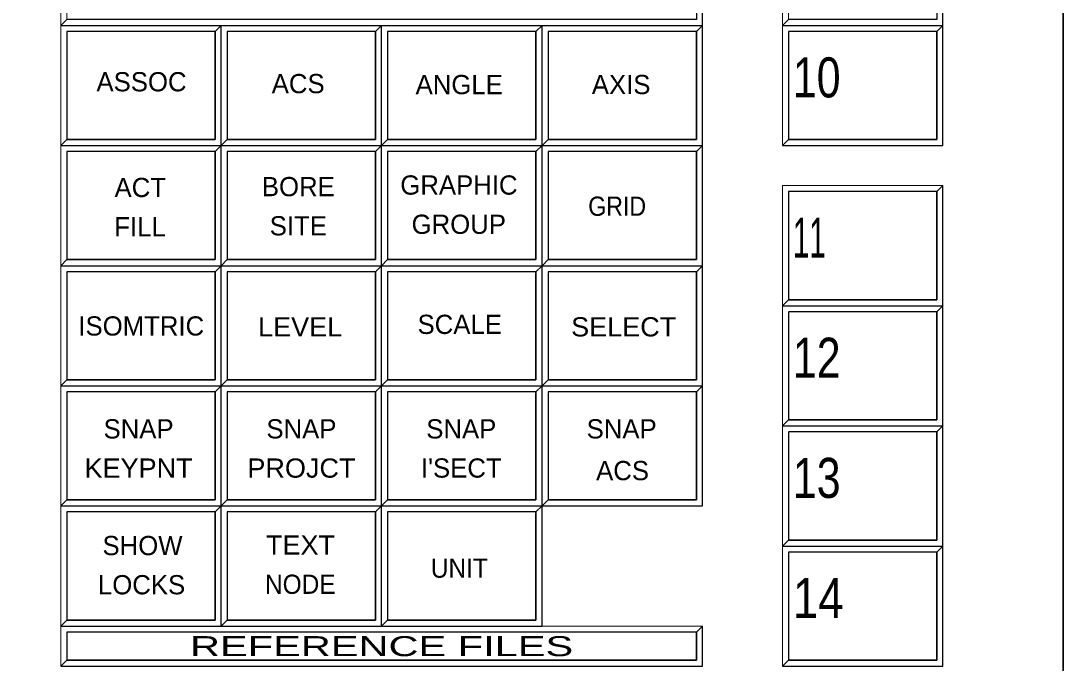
# Model space of a CAD drawing. Extents: x 95906.8 to 95923.6, y 90964.8 to 90972.8.
# Drawn here: x 95916.232 to 95918.832, y 90967.969 to 90969.573 of the extents above; entities that cross this region are included whole.
import ezdxf
from ezdxf.enums import TextEntityAlignment as Align

# ---------------------------------------------------------------- set-up
doc = ezdxf.new("R2010")
doc.units = 0
doc.header["$LTSCALE"] = 0.019
for name, color, linetype, lineweight in [('11', 7, 'Continuous', 25), ('12', 7, 'Continuous', 25), ('2', 7, 'Continuous', 13), ('21', 7, 'Continuous', 25), ('3', 7, 'Continuous', 25), ('6', 7, 'Continuous', 25), ('7', 7, 'Continuous', 35)]:
    doc.layers.add(name, color=color, linetype=linetype, lineweight=lineweight)

msp = doc.modelspace()

# ---------------------------------------------------------------- linework, layer by layer
at = {"layer": '11'}
for points in [[(95916.3473, 90969.2767), (95916.7173, 90969.2767), (95916.7173, 90969.5467), (95916.3473, 90969.5467)], [(95916.7473, 90969.2767), (95917.1173, 90969.2767), (95917.1173, 90969.5467), (95916.7473, 90969.5467)], [(95917.1473, 90969.2767), (95917.5173, 90969.2767), (95917.5173, 90969.5467), (95917.1473, 90969.5467)], [(95918.1473, 90969.2767), (95918.5173, 90969.2767), (95918.5173, 90969.5467), (95918.1473, 90969.5467)], [(95916.3473, 90968.9767), (95916.7173, 90968.9767), (95916.7173, 90969.2467), (95916.3473, 90969.2467)], [(95916.7473, 90968.9767), (95917.1173, 90968.9767), (95917.1173, 90969.2467), (95916.7473, 90969.2467)], [(95917.1473, 90968.9767), (95917.5173, 90968.9767), (95917.5173, 90969.2467), (95917.1473, 90969.2467)], [(95917.5473, 90968.9767), (95917.9173, 90968.9767), (95917.9173, 90969.2467), (95917.5473, 90969.2467)], [(95918.1473, 90968.8767), (95918.5173, 90968.8767), (95918.5173, 90969.1467), (95918.1473, 90969.1467)], [(95916.3473, 90968.6767), (95916.7173, 90968.6767), (95916.7173, 90968.9467), (95916.3473, 90968.9467)], [(95916.7473, 90968.6767), (95917.1173, 90968.6767), (95917.1173, 90968.9467), (95916.7473, 90968.9467)], [(95917.1473, 90968.6767), (95917.5173, 90968.6767), (95917.5173, 90968.9467), (95917.1473, 90968.9467)], [(95917.1473, 90968.6767), (95917.5173, 90968.6767), (95917.5173, 90968.9467), (95917.1473, 90968.9467)], [(95917.5473, 90968.6767), (95917.9173, 90968.6767), (95917.9173, 90968.9467), (95917.5473, 90968.9467)], [(95918.1473, 90968.5767), (95918.5173, 90968.5767), (95918.5173, 90968.8467), (95918.1473, 90968.8467)], [(95916.3473, 90968.3767), (95916.7173, 90968.3767), (95916.7173, 90968.6467), (95916.3473, 90968.6467)], [(95916.7473, 90968.3767), (95917.1173, 90968.3767), (95917.1173, 90968.6467), (95916.7473, 90968.6467)], [(95916.7473, 90968.3767), (95917.1173, 90968.3767), (95917.1173, 90968.6467), (95916.7473, 90968.6467)], [(95917.1473, 90968.3767), (95917.5173, 90968.3767), (95917.5173, 90968.6467), (95917.1473, 90968.6467)], [(95917.1473, 90968.3767), (95917.5173, 90968.3767), (95917.5173, 90968.6467), (95917.1473, 90968.6467)], [(95917.5473, 90968.3767), (95917.9173, 90968.3767), (95917.9173, 90968.6467), (95917.5473, 90968.6467)], [(95917.5473, 90968.3767), (95917.9173, 90968.3767), (95917.9173, 90968.6467), (95917.5473, 90968.6467)], [(95918.1473, 90968.2767), (95918.5173, 90968.2767), (95918.5173, 90968.5467), (95918.1473, 90968.5467)], [(95916.3473, 90968.0767), (95916.7173, 90968.0767), (95916.7173, 90968.3467), (95916.3473, 90968.3467)], [(95916.7473, 90968.0767), (95917.1173, 90968.0767), (95917.1173, 90968.3467), (95916.7473, 90968.3467)], [(95917.1473, 90968.0767), (95917.5173, 90968.0767), (95917.5173, 90968.3467), (95917.1473, 90968.3467)], [(95918.1473, 90967.9767), (95918.5173, 90967.9767), (95918.5173, 90968.2467), (95918.1473, 90968.2467)]]:
    msp.add_lwpolyline(points, close=True, dxfattribs=at)
at = {"layer": '12'}
msp.add_lwpolyline([(95917.5473, 90969.2767), (95917.9173, 90969.2767), (95917.9173, 90969.5467), (95917.5473, 90969.5467)], close=True, dxfattribs=at)
at = {"layer": '2'}
for points in [[(95918.1323, 90969.8617), (95918.1323, 90969.5617), (95918.1473, 90969.5767), (95918.1473, 90969.8467), (95918.5173, 90969.8467), (95918.5323, 90969.8617)], [(95916.3323, 90969.6617), (95916.3323, 90969.5617), (95916.3473, 90969.5767), (95916.3473, 90969.6467), (95917.9173, 90969.6467), (95917.9323, 90969.6617)], [(95916.3323, 90969.5617), (95916.3323, 90969.2617), (95916.3473, 90969.2767), (95916.3473, 90969.5467), (95916.7173, 90969.5467), (95916.7323, 90969.5617)], [(95916.7323, 90969.5617), (95916.7323, 90969.2617), (95916.7473, 90969.2767), (95916.7473, 90969.5467), (95917.1173, 90969.5467), (95917.1323, 90969.5617)], [(95917.1323, 90969.5617), (95917.1323, 90969.2617), (95917.1473, 90969.2767), (95917.1473, 90969.5467), (95917.5173, 90969.5467), (95917.5323, 90969.5617)], [(95917.5323, 90969.5617), (95917.5323, 90969.2617), (95917.5473, 90969.2767), (95917.5473, 90969.5467), (95917.9173, 90969.5467), (95917.9323, 90969.5617)], [(95918.1323, 90969.5617), (95918.1323, 90969.2617), (95918.1473, 90969.2767), (95918.1473, 90969.5467), (95918.5173, 90969.5467), (95918.5323, 90969.5617)], [(95916.3323, 90969.2617), (95916.3323, 90968.9617), (95916.3473, 90968.9767), (95916.3473, 90969.2467), (95916.7173, 90969.2467), (95916.7323, 90969.2617)], [(95916.7323, 90969.2617), (95916.7323, 90968.9617), (95916.7473, 90968.9767), (95916.7473, 90969.2467), (95917.1173, 90969.2467), (95917.1323, 90969.2617)], [(95917.1323, 90969.2617), (95917.1323, 90968.9617), (95917.1473, 90968.9767), (95917.1473, 90969.2467), (95917.5173, 90969.2467), (95917.5323, 90969.2617)], [(95917.5323, 90969.2617), (95917.5323, 90968.9617), (95917.5473, 90968.9767), (95917.5473, 90969.2467), (95917.9173, 90969.2467), (95917.9323, 90969.2617)], [(95918.1323, 90969.1617), (95918.1323, 90968.8617), (95918.1473, 90968.8767), (95918.1473, 90969.1467), (95918.5173, 90969.1467), (95918.5323, 90969.1617)], [(95916.3323, 90968.9617), (95916.3323, 90968.6617), (95916.3473, 90968.6767), (95916.3473, 90968.9467), (95916.7173, 90968.9467), (95916.7323, 90968.9617)], [(95916.7323, 90968.9617), (95916.7323, 90968.6617), (95916.7473, 90968.6767), (95916.7473, 90968.9467), (95917.1173, 90968.9467), (95917.1323, 90968.9617)], [(95917.1323, 90968.9617), (95917.1323, 90968.6617), (95917.1473, 90968.6767), (95917.1473, 90968.9467), (95917.5173, 90968.9467), (95917.5323, 90968.9617)], [(95917.1323, 90968.9617), (95917.1323, 90968.6617), (95917.1473, 90968.6767), (95917.1473, 90968.9467), (95917.5173, 90968.9467), (95917.5323, 90968.9617)], [(95917.5323, 90968.9617), (95917.5323, 90968.6617), (95917.5473, 90968.6767), (95917.5473, 90968.9467), (95917.9173, 90968.9467), (95917.9323, 90968.9617)], [(95918.1323, 90968.8617), (95918.1323, 90968.5617), (95918.1473, 90968.5767), (95918.1473, 90968.8467), (95918.5173, 90968.8467), (95918.5323, 90968.8617)], [(95916.3323, 90968.6617), (95916.3323, 90968.3617), (95916.3473, 90968.3767), (95916.3473, 90968.6467), (95916.7173, 90968.6467), (95916.7323, 90968.6617)], [(95916.7323, 90968.6617), (95916.7323, 90968.3617), (95916.7473, 90968.3767), (95916.7473, 90968.6467), (95917.1173, 90968.6467), (95917.1323, 90968.6617)], [(95916.7323, 90968.6617), (95916.7323, 90968.3617), (95916.7473, 90968.3767), (95916.7473, 90968.6467), (95917.1173, 90968.6467), (95917.1323, 90968.6617)], [(95917.1323, 90968.6617), (95917.1323, 90968.3617), (95917.1473, 90968.3767), (95917.1473, 90968.6467), (95917.5173, 90968.6467), (95917.5323, 90968.6617)], [(95917.1323, 90968.6617), (95917.1323, 90968.3617), (95917.1473, 90968.3767), (95917.1473, 90968.6467), (95917.5173, 90968.6467), (95917.5323, 90968.6617)], [(95917.5323, 90968.6617), (95917.5323, 90968.3617), (95917.5473, 90968.3767), (95917.5473, 90968.6467), (95917.9173, 90968.6467), (95917.9323, 90968.6617)], [(95917.5323, 90968.6617), (95917.5323, 90968.3617), (95917.5473, 90968.3767), (95917.5473, 90968.6467), (95917.9173, 90968.6467), (95917.9323, 90968.6617)], [(95918.1323, 90968.5617), (95918.1323, 90968.2617), (95918.1473, 90968.2767), (95918.1473, 90968.5467), (95918.5173, 90968.5467), (95918.5323, 90968.5617)], [(95916.3323, 90968.3617), (95916.3323, 90968.0617), (95916.3473, 90968.0767), (95916.3473, 90968.3467), (95916.7173, 90968.3467), (95916.7323, 90968.3617)], [(95916.7323, 90968.3617), (95916.7323, 90968.0617), (95916.7473, 90968.0767), (95916.7473, 90968.3467), (95917.1173, 90968.3467), (95917.1323, 90968.3617)], [(95917.1323, 90968.3617), (95917.1323, 90968.0617), (95917.1473, 90968.0767), (95917.1473, 90968.3467), (95917.5173, 90968.3467), (95917.5323, 90968.3617)], [(95918.1323, 90968.2617), (95918.1323, 90967.9617), (95918.1473, 90967.9767), (95918.1473, 90968.2467), (95918.5173, 90968.2467), (95918.5323, 90968.2617)], [(95916.3323, 90968.0617), (95916.3323, 90967.9617), (95916.3473, 90967.9767), (95916.3473, 90968.0467), (95917.9173, 90968.0467), (95917.9323, 90968.0617)]]:
    msp.add_lwpolyline(points, close=True, dxfattribs=at)
at = {"layer": '21'}
msp.add_lwpolyline([(95916.3473, 90967.9767), (95917.9173, 90967.9767), (95917.9173, 90968.0467), (95916.3473, 90968.0467)], close=True, dxfattribs=at)
at = {"layer": '3'}
for points in [[(95918.1323, 90969.5617), (95918.5323, 90969.5617), (95918.5323, 90969.8617), (95918.5173, 90969.8467), (95918.5173, 90969.5767), (95918.1473, 90969.5767)], [(95916.3323, 90969.5617), (95917.9323, 90969.5617), (95917.9323, 90969.6617), (95917.9173, 90969.6467), (95917.9173, 90969.5767), (95916.3473, 90969.5767)], [(95916.3323, 90969.2617), (95916.7323, 90969.2617), (95916.7323, 90969.5617), (95916.7173, 90969.5467), (95916.7173, 90969.2767), (95916.3473, 90969.2767)], [(95916.7323, 90969.2617), (95917.1323, 90969.2617), (95917.1323, 90969.5617), (95917.1173, 90969.5467), (95917.1173, 90969.2767), (95916.7473, 90969.2767)], [(95917.1323, 90969.2617), (95917.5323, 90969.2617), (95917.5323, 90969.5617), (95917.5173, 90969.5467), (95917.5173, 90969.2767), (95917.1473, 90969.2767)], [(95917.5323, 90969.2617), (95917.9323, 90969.2617), (95917.9323, 90969.5617), (95917.9173, 90969.5467), (95917.9173, 90969.2767), (95917.5473, 90969.2767)], [(95918.1323, 90969.2617), (95918.5323, 90969.2617), (95918.5323, 90969.5617), (95918.5173, 90969.5467), (95918.5173, 90969.2767), (95918.1473, 90969.2767)], [(95916.3323, 90968.9617), (95916.7323, 90968.9617), (95916.7323, 90969.2617), (95916.7173, 90969.2467), (95916.7173, 90968.9767), (95916.3473, 90968.9767)], [(95916.7323, 90968.9617), (95917.1323, 90968.9617), (95917.1323, 90969.2617), (95917.1173, 90969.2467), (95917.1173, 90968.9767), (95916.7473, 90968.9767)], [(95917.1323, 90968.9617), (95917.5323, 90968.9617), (95917.5323, 90969.2617), (95917.5173, 90969.2467), (95917.5173, 90968.9767), (95917.1473, 90968.9767)], [(95917.5323, 90968.9617), (95917.9323, 90968.9617), (95917.9323, 90969.2617), (95917.9173, 90969.2467), (95917.9173, 90968.9767), (95917.5473, 90968.9767)], [(95918.1323, 90968.8617), (95918.5323, 90968.8617), (95918.5323, 90969.1617), (95918.5173, 90969.1467), (95918.5173, 90968.8767), (95918.1473, 90968.8767)], [(95916.3323, 90968.6617), (95916.7323, 90968.6617), (95916.7323, 90968.9617), (95916.7173, 90968.9467), (95916.7173, 90968.6767), (95916.3473, 90968.6767)], [(95916.7323, 90968.6617), (95917.1323, 90968.6617), (95917.1323, 90968.9617), (95917.1173, 90968.9467), (95917.1173, 90968.6767), (95916.7473, 90968.6767)], [(95917.1323, 90968.6617), (95917.5323, 90968.6617), (95917.5323, 90968.9617), (95917.5173, 90968.9467), (95917.5173, 90968.6767), (95917.1473, 90968.6767)], [(95917.1323, 90968.6617), (95917.5323, 90968.6617), (95917.5323, 90968.9617), (95917.5173, 90968.9467), (95917.5173, 90968.6767), (95917.1473, 90968.6767)], [(95917.5323, 90968.6617), (95917.9323, 90968.6617), (95917.9323, 90968.9617), (95917.9173, 90968.9467), (95917.9173, 90968.6767), (95917.5473, 90968.6767)], [(95918.1323, 90968.5617), (95918.5323, 90968.5617), (95918.5323, 90968.8617), (95918.5173, 90968.8467), (95918.5173, 90968.5767), (95918.1473, 90968.5767)], [(95916.3323, 90968.3617), (95916.7323, 90968.3617), (95916.7323, 90968.6617), (95916.7173, 90968.6467), (95916.7173, 90968.3767), (95916.3473, 90968.3767)], [(95916.7323, 90968.3617), (95917.1323, 90968.3617), (95917.1323, 90968.6617), (95917.1173, 90968.6467), (95917.1173, 90968.3767), (95916.7473, 90968.3767)], [(95916.7323, 90968.3617), (95917.1323, 90968.3617), (95917.1323, 90968.6617), (95917.1173, 90968.6467), (95917.1173, 90968.3767), (95916.7473, 90968.3767)], [(95917.1323, 90968.3617), (95917.5323, 90968.3617), (95917.5323, 90968.6617), (95917.5173, 90968.6467), (95917.5173, 90968.3767), (95917.1473, 90968.3767)], [(95917.1323, 90968.3617), (95917.5323, 90968.3617), (95917.5323, 90968.6617), (95917.5173, 90968.6467), (95917.5173, 90968.3767), (95917.1473, 90968.3767)], [(95917.5323, 90968.3617), (95917.9323, 90968.3617), (95917.9323, 90968.6617), (95917.9173, 90968.6467), (95917.9173, 90968.3767), (95917.5473, 90968.3767)], [(95917.5323, 90968.3617), (95917.9323, 90968.3617), (95917.9323, 90968.6617), (95917.9173, 90968.6467), (95917.9173, 90968.3767), (95917.5473, 90968.3767)], [(95918.1323, 90968.2617), (95918.5323, 90968.2617), (95918.5323, 90968.5617), (95918.5173, 90968.5467), (95918.5173, 90968.2767), (95918.1473, 90968.2767)], [(95916.3323, 90968.0617), (95916.7323, 90968.0617), (95916.7323, 90968.3617), (95916.7173, 90968.3467), (95916.7173, 90968.0767), (95916.3473, 90968.0767)], [(95916.7323, 90968.0617), (95917.1323, 90968.0617), (95917.1323, 90968.3617), (95917.1173, 90968.3467), (95917.1173, 90968.0767), (95916.7473, 90968.0767)], [(95917.1323, 90968.0617), (95917.5323, 90968.0617), (95917.5323, 90968.3617), (95917.5173, 90968.3467), (95917.5173, 90968.0767), (95917.1473, 90968.0767)], [(95918.1323, 90967.9617), (95918.5323, 90967.9617), (95918.5323, 90968.2617), (95918.5173, 90968.2467), (95918.5173, 90967.9767), (95918.1473, 90967.9767)], [(95916.3323, 90967.9617), (95917.9323, 90967.9617), (95917.9323, 90968.0617), (95917.9173, 90968.0467), (95917.9173, 90967.9767), (95916.3473, 90967.9767)]]:
    msp.add_lwpolyline(points, close=True, dxfattribs=at)
at = {"layer": '7'}
msp.add_lwpolyline([(95906.8323, 90972.7617), (95918.8323, 90972.7617), (95918.8323, 90964.7617), (95906.8323, 90964.7617)], close=True, dxfattribs=at)

# ---------------------------------------------------------------- texts
at = {"layer": '21', "width": 1.55}
msp.add_text('    REFERENCE FILES    ', height=0.04999, dxfattribs=at).set_placement((95917.1322, 90967.9867), align=Align.CENTER)
at = {"layer": '6'}
for s, width, p in [('10', 0.8, (95918.1581, 90969.3818)), ('11', 0.55, (95918.1581, 90968.9818)), ('12', 0.8, (95918.1581, 90968.6818)), ('13', 0.8, (95918.1581, 90968.3818)), ('14', 0.85, (95918.1581, 90968.0818))]:
    msp.add_text(s, height=0.1, dxfattribs=dict(at, width=width)).set_placement(p)
for s, p in [('ASSOC', (95916.5333, 90969.3969)), ('ACS', (95916.9241, 90969.3923)), ('ANGLE', (95917.3258, 90969.3899)), ('AXIS', (95917.7297, 90969.39)), ('ACT', (95916.5302, 90969.133)), ('BORE', (95916.9245, 90969.1351)), ('GRAPHIC', (95917.3251, 90969.1391)), ('SITE', (95916.9244, 90969.0373)), ('GROUP', (95917.3247, 90969.0411)), ('FILL', (95916.5295, 90969.035)), ('ISOMTRIC', (95916.5327, 90968.7872)), ('SCALE', (95917.3271, 90968.7912)), ('SNAP', (95916.526, 90968.5303)), ('SNAP', (95916.9322, 90968.5303)), ('SNAP', (95917.331, 90968.5303)), ('SNAP', (95917.731, 90968.5303)), ("I'SECT", (95917.331, 90968.4325)), ('ACS', (95917.7333, 90968.4261)), ('SHOW', (95916.5358, 90968.2389)), ('LOCKS', (95916.5335, 90968.1411))]:
    msp.add_text(s, height=0.048, dxfattribs=at).set_placement(p, align=Align.CENTER)
for s, width, p in [('GRID', 0.9, (95917.7198, 90969.0862)), ('LEVEL', 1.05, (95916.929, 90968.7849)), ('SELECT', 1.05, (95917.7361, 90968.785)), ('KEYPNT', 1.05, (95916.526, 90968.4323)), ('PROJCT', 1.05, (95916.9322, 90968.4323)), ('TEXT', 1.05, (95916.9298, 90968.2403)), ('UNIT', 0.95, (95917.3261, 90968.1825)), ('NODE', 0.95, (95916.9294, 90968.1423))]:
    msp.add_text(s, height=0.048, dxfattribs=dict(at, width=width)).set_placement(p, align=Align.CENTER)

doc.saveas('drawing.dxf')
